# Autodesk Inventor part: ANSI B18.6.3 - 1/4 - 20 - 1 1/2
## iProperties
Comments: To add or edit properties for Autodesk Inventor files, use iProperties.
Created: 2004-12
Part Number: ANSI B18.6.3 - 1/4 - 20 - 1 1/2
Vendor: Autodesk Inc.
Document SubType Name: Modeling
Designer: John Blackburn
Material: Default
Description: Plain Hex Head Machine Screw
Standard: ANSI B18.6.3
Alert: To add or edit properties for Autodesk Inventor files, use iProperties.
Control State: 0
Master: False
Checked Out: False
Shininess: 64.0
Length Units: 11272
Angle Units: 11279
Time Units: 11290
Mass Units: 11286
Length Display Precision: 3
Angle Display Precision: 2
Compacted: True
EGR: 3
Classification: un/spsc 31161513
Density: 0.0
Volumn: 0.0
Area: 0.0
PropertySet Name: Model Information
Author: John Blackburn
Revision Number: 8
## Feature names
1. Body [Revolution]
2. Head [Extrusion]
3. Chamfer1 [Revolution]
4. Chamfer2
